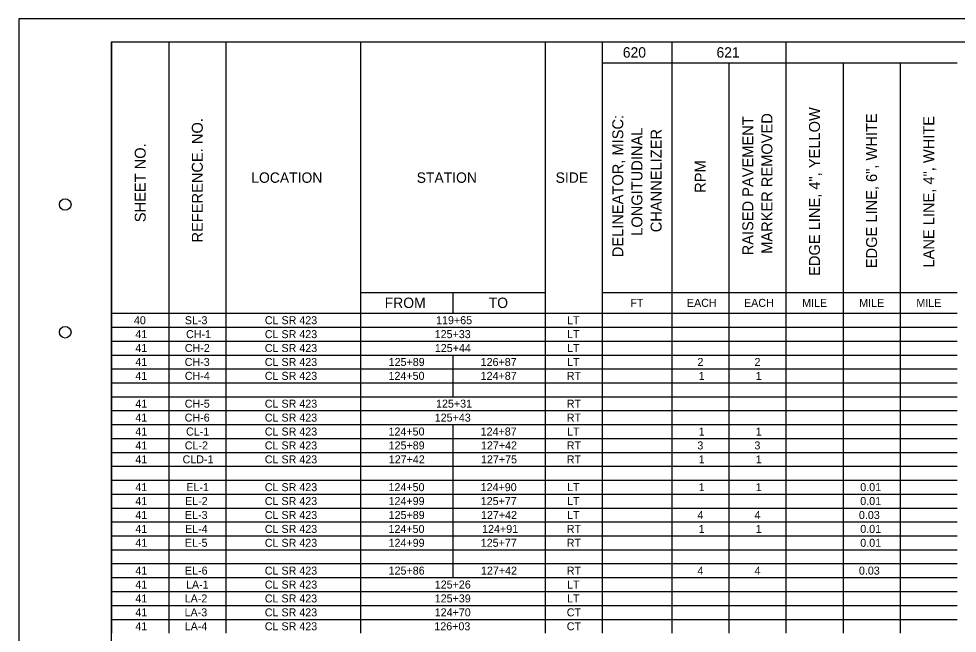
# Model space of a CAD drawing. Extents: x 10.3 to 44.3, y 3.4 to 25.4.
# Drawn here: x 10.31 to 30.51, y 12.17 to 25.4 of the extents above; entities that cross this region are included whole.
import ezdxf

# ---------------------------------------------------------------- set-up
doc = ezdxf.new("R2010")
doc.units = 0
for name, color, linetype in [('SH_Border', 7, 'Continuous'), ('SH_Cut_Line', 7, 'Continuous'), ('SH_Text', 7, 'Continuous')]:
    doc.layers.add(name, color=color, linetype=linetype)

msp = doc.modelspace()

# ---------------------------------------------------------------- linework, layer by layer
at = {"layer": 'SH_Border'}
msp.add_lwpolyline([(12.306, 24.905), (43.806, 24.905), (43.806, 3.905), (12.306, 3.905)], close=True, dxfattribs=at)
for centre in [(11.306, 21.405), (11.306, 18.655)]:
    msp.add_circle(centre, 0.125, dxfattribs=at)
at = {"layer": 'SH_Cut_Line'}
msp.add_lwpolyline([(10.306, 3.405), (44.306, 3.405), (44.306, 25.405), (10.306, 25.405)], close=True, dxfattribs=at)
at = {"layer": 'SH_Text'}
for p, q in [((12.306, 24.905), (14.765, 24.905)), ((12.306, 24.905), (12.306, 12.173)), ((13.536, 24.905), (13.536, 12.173)), ((14.765, 24.905), (21.637, 24.905)), ((14.765, 24.905), (14.765, 12.173)), ((17.665, 24.905), (17.665, 12.173)), ((21.637, 24.905), (26.823, 24.905)), ((21.637, 24.905), (21.637, 12.173)), ((22.867, 24.905), (22.867, 12.173)), ((24.364, 24.905), (24.364, 12.173)), ((26.823, 24.905), (28.053, 24.905)), ((26.823, 24.905), (26.823, 12.173)), ((28.053, 24.905), (30.512, 24.905)), ((22.867, 24.455), (26.823, 24.455)), ((25.594, 24.455), (25.594, 12.173)), ((26.823, 24.455), (28.053, 24.455)), ((28.053, 24.455), (30.512, 24.455)), ((28.053, 24.455), (28.053, 12.173)), ((29.282, 24.455), (29.282, 12.173)), ((17.665, 19.512), (21.637, 19.512)), ((19.651, 19.512), (19.651, 19.063)), ((22.867, 19.512), (26.823, 19.512)), ((26.823, 19.512), (28.053, 19.512)), ((28.053, 19.512), (30.512, 19.512)), ((12.306, 19.063), (14.765, 19.063)), ((14.765, 19.063), (21.637, 19.063)), ((21.637, 19.063), (26.823, 19.063)), ((26.823, 19.063), (28.053, 19.063)), ((28.053, 19.063), (30.512, 19.063)), ((12.306, 18.763), (14.765, 18.763)), ((14.765, 18.763), (21.637, 18.763)), ((21.637, 18.763), (26.823, 18.763)), ((26.823, 18.763), (28.053, 18.763)), ((28.053, 18.763), (30.512, 18.763)), ((12.306, 18.464), (14.765, 18.464)), ((14.765, 18.464), (21.637, 18.464)), ((21.637, 18.464), (26.823, 18.464)), ((26.823, 18.464), (28.053, 18.464)), ((28.053, 18.464), (30.512, 18.464)), ((12.306, 18.164), (14.765, 18.164)), ((14.765, 18.164), (21.637, 18.164)), ((19.651, 18.164), (19.651, 17.265)), ((21.637, 18.164), (26.823, 18.164)), ((26.823, 18.164), (28.053, 18.164)), ((28.053, 18.164), (30.512, 18.164)), ((12.306, 17.865), (14.765, 17.865)), ((14.765, 17.865), (21.637, 17.865)), ((21.637, 17.865), (26.823, 17.865)), ((26.823, 17.865), (28.053, 17.865)), ((28.053, 17.865), (30.512, 17.865)), ((12.306, 17.565), (14.765, 17.565)), ((14.765, 17.565), (21.637, 17.565)), ((21.637, 17.565), (26.823, 17.565)), ((26.823, 17.565), (28.053, 17.565)), ((28.053, 17.565), (30.512, 17.565)), ((12.306, 17.265), (14.765, 17.265)), ((14.765, 17.265), (21.637, 17.265)), ((21.637, 17.265), (26.823, 17.265)), ((26.823, 17.265), (28.053, 17.265)), ((28.053, 17.265), (30.512, 17.265)), ((12.306, 16.966), (14.765, 16.966)), ((14.765, 16.966), (21.637, 16.966)), ((21.637, 16.966), (26.823, 16.966)), ((26.823, 16.966), (28.053, 16.966)), ((28.053, 16.966), (30.512, 16.966)), ((12.306, 16.666), (14.765, 16.666)), ((14.765, 16.666), (21.637, 16.666)), ((19.651, 16.666), (19.651, 13.371)), ((21.637, 16.666), (26.823, 16.666)), ((26.823, 16.666), (28.053, 16.666)), ((28.053, 16.666), (30.512, 16.666)), ((12.306, 16.367), (14.765, 16.367)), ((14.765, 16.367), (21.637, 16.367)), ((21.637, 16.367), (26.823, 16.367)), ((26.823, 16.367), (28.053, 16.367)), ((28.053, 16.367), (30.512, 16.367)), ((12.306, 16.067), (14.765, 16.067)), ((14.765, 16.067), (21.637, 16.067)), ((21.637, 16.067), (26.823, 16.067)), ((26.823, 16.067), (28.053, 16.067)), ((28.053, 16.067), (30.512, 16.067)), ((12.306, 15.768), (14.765, 15.768)), ((14.765, 15.768), (21.637, 15.768)), ((21.637, 15.768), (26.823, 15.768)), ((26.823, 15.768), (28.053, 15.768)), ((28.053, 15.768), (30.512, 15.768)), ((12.306, 15.468), (14.765, 15.468)), ((14.765, 15.468), (21.637, 15.468)), ((21.637, 15.468), (26.823, 15.468)), ((26.823, 15.468), (28.053, 15.468)), ((28.053, 15.468), (30.512, 15.468)), ((12.306, 15.168), (14.765, 15.168)), ((14.765, 15.168), (21.637, 15.168)), ((21.637, 15.168), (26.823, 15.168)), ((26.823, 15.168), (28.053, 15.168)), ((28.053, 15.168), (30.512, 15.168)), ((12.306, 14.869), (14.765, 14.869)), ((14.765, 14.869), (21.637, 14.869)), ((21.637, 14.869), (26.823, 14.869)), ((26.823, 14.869), (28.053, 14.869)), ((28.053, 14.869), (30.512, 14.869)), ((12.306, 14.569), (14.765, 14.569)), ((14.765, 14.569), (21.637, 14.569)), ((21.637, 14.569), (26.823, 14.569)), ((26.823, 14.569), (28.053, 14.569)), ((28.053, 14.569), (30.512, 14.569)), ((12.306, 14.27), (14.765, 14.27)), ((14.765, 14.27), (21.637, 14.27)), ((21.637, 14.27), (26.823, 14.27)), ((26.823, 14.27), (28.053, 14.27)), ((28.053, 14.27), (30.512, 14.27)), ((12.306, 13.97), (14.765, 13.97)), ((14.765, 13.97), (21.637, 13.97)), ((21.637, 13.97), (26.823, 13.97)), ((26.823, 13.97), (28.053, 13.97)), ((28.053, 13.97), (30.512, 13.97)), ((12.306, 13.671), (14.765, 13.671)), ((14.765, 13.671), (21.637, 13.671)), ((21.637, 13.671), (26.823, 13.671)), ((26.823, 13.671), (28.053, 13.671)), ((28.053, 13.671), (30.512, 13.671)), ((12.306, 13.371), (14.765, 13.371)), ((14.765, 13.371), (21.637, 13.371)), ((21.637, 13.371), (26.823, 13.371)), ((26.823, 13.371), (28.053, 13.371)), ((28.053, 13.371), (30.512, 13.371)), ((12.306, 13.071), (14.765, 13.071)), ((14.765, 13.071), (21.637, 13.071)), ((21.637, 13.071), (26.823, 13.071)), ((26.823, 13.071), (28.053, 13.071)), ((28.053, 13.071), (30.512, 13.071)), ((12.306, 12.772), (14.765, 12.772)), ((14.765, 12.772), (21.637, 12.772)), ((21.637, 12.772), (26.823, 12.772)), ((26.823, 12.772), (28.053, 12.772)), ((28.053, 12.772), (30.512, 12.772)), ((12.306, 12.472), (14.765, 12.472)), ((14.765, 12.472), (21.637, 12.472)), ((21.637, 12.472), (26.823, 12.472)), ((26.823, 12.472), (28.053, 12.472)), ((28.053, 12.472), (30.512, 12.472))]:
    msp.add_line(p, q, dxfattribs=at)

# ---------------------------------------------------------------- texts
for s, height, p in [('620', 0.2239, (23.311, 24.568)), ('621', 0.2239, (25.328, 24.568)), ('LOCATION', 0.2239, (15.312, 21.872)), ('STATION', 0.2239, (18.873, 21.872)), ('SIDE', 0.2239, (21.865, 21.872)), ('FROM', 0.2239, (18.185, 19.176)), ('TO', 0.2239, (20.424, 19.176)), ('FT', 0.1723, (23.473, 19.201)), ('EACH', 0.1723, (24.692, 19.201)), ('EACH', 0.1723, (25.921, 19.201)), ('MILE', 0.1723, (27.173, 19.201)), ('MILE', 0.1723, (28.402, 19.201)), ('MILE', 0.1723, (29.632, 19.201)), ('40', 0.1723, (12.785, 18.827)), ('SL-3', 0.1723, (13.882, 18.827)), ('CL SR 423', 0.1723, (15.604, 18.827)), ('119+65', 0.1723, (19.291, 18.827)), ('LT', 0.1723, (22.11, 18.827)), ('41', 0.1723, (12.816, 18.527)), ('CH-1', 0.1723, (13.908, 18.527)), ('CL SR 423', 0.1723, (15.604, 18.527)), ('125+33', 0.1723, (19.261, 18.527)), ('LT', 0.1723, (22.11, 18.527)), ('41', 0.1723, (12.816, 18.228)), ('CH-2', 0.1723, (13.881, 18.228)), ('CL SR 423', 0.1723, (15.604, 18.228)), ('125+44', 0.1723, (19.264, 18.228)), ('LT', 0.1723, (22.11, 18.228)), ('41', 0.1723, (12.816, 17.928)), ('CH-3', 0.1723, (13.879, 17.928)), ('CL SR 423', 0.1723, (15.604, 17.928)), ('125+89', 0.1723, (18.27, 17.928)), ('126+87', 0.1723, (20.251, 17.928)), ('LT', 0.1723, (22.11, 17.928)), ('2', 0.172, (24.918, 17.928)), ('2', 0.172, (26.147, 17.928)), ('41', 0.1723, (12.816, 17.629)), ('CH-4', 0.1723, (13.882, 17.629)), ('CL SR 423', 0.1723, (15.604, 17.629)), ('124+50', 0.1723, (18.267, 17.629)), ('124+87', 0.1723, (20.251, 17.629)), ('RT', 0.1723, (22.105, 17.629)), ('1', 0.172, (24.945, 17.629)), ('1', 0.172, (26.174, 17.629)), ('41', 0.1723, (12.816, 17.03)), ('CH-5', 0.1723, (13.88, 17.03)), ('CL SR 423', 0.1723, (15.604, 17.03)), ('125+31', 0.1723, (19.29, 17.03)), ('RT', 0.1723, (22.105, 17.03)), ('41', 0.1723, (12.816, 16.73)), ('CH-6', 0.1723, (13.879, 16.73)), ('CL SR 423', 0.1723, (15.604, 16.73)), ('125+43', 0.1723, (19.262, 16.73)), ('RT', 0.1723, (22.105, 16.73)), ('41', 0.1723, (12.816, 16.43)), ('CL-1', 0.1723, (13.908, 16.43)), ('CL SR 423', 0.1723, (15.604, 16.43)), ('124+50', 0.1723, (18.267, 16.43)), ('124+87', 0.1723, (20.251, 16.43)), ('LT', 0.1723, (22.11, 16.43)), ('1', 0.172, (24.945, 16.43)), ('1', 0.172, (26.174, 16.43)), ('41', 0.1723, (12.816, 16.131)), ('CL-2', 0.1723, (13.881, 16.131)), ('CL SR 423', 0.1723, (15.604, 16.131)), ('125+89', 0.1723, (18.27, 16.131)), ('127+42', 0.1723, (20.258, 16.131)), ('RT', 0.1723, (22.105, 16.131)), ('3', 0.172, (24.916, 16.131)), ('3', 0.172, (26.145, 16.131)), ('41', 0.1723, (12.816, 15.831)), ('CLD-1', 0.1723, (13.833, 15.831)), ('CL SR 423', 0.1723, (15.604, 15.831)), ('127+42', 0.1723, (18.272, 15.831)), ('127+75', 0.1723, (20.258, 15.831)), ('RT', 0.1723, (22.105, 15.831)), ('1', 0.172, (24.945, 15.831)), ('1', 0.172, (26.174, 15.831)), ('41', 0.1723, (12.816, 15.232)), ('EL-1', 0.1723, (13.913, 15.232)), ('CL SR 423', 0.1723, (15.604, 15.232)), ('124+50', 0.1723, (18.267, 15.232)), ('124+90', 0.1723, (20.251, 15.232)), ('LT', 0.1723, (22.11, 15.232)), ('1', 0.172, (24.945, 15.232)), ('1', 0.172, (26.174, 15.232)), ('0.01', 0.1723, (28.424, 15.232)), ('41', 0.1723, (12.816, 14.933)), ('EL-2', 0.1723, (13.886, 14.933)), ('CL SR 423', 0.1723, (15.604, 14.933)), ('124+99', 0.1723, (18.268, 14.933)), ('125+77', 0.1723, (20.253, 14.933)), ('LT', 0.1723, (22.11, 14.933)), ('0.01', 0.1723, (28.424, 14.933)), ('41', 0.1723, (12.816, 14.633)), ('EL-3', 0.1723, (13.884, 14.633)), ('CL SR 423', 0.1723, (15.604, 14.633)), ('125+89', 0.1723, (18.27, 14.633)), ('127+42', 0.1723, (20.258, 14.633)), ('LT', 0.1723, (22.11, 14.633)), ('4', 0.172, (24.919, 14.633)), ('4', 0.172, (26.148, 14.633)), ('0.03', 0.1723, (28.395, 14.633)), ('41', 0.1723, (12.816, 14.333)), ('EL-4', 0.1723, (13.886, 14.333)), ('CL SR 423', 0.1723, (15.604, 14.333)), ('124+50', 0.1723, (18.267, 14.333)), ('124+91', 0.1723, (20.282, 14.333)), ('RT', 0.1723, (22.105, 14.333)), ('1', 0.172, (24.945, 14.333)), ('1', 0.172, (26.174, 14.333)), ('0.01', 0.1723, (28.424, 14.333)), ('41', 0.1723, (12.816, 14.034)), ('EL-5', 0.1723, (13.884, 14.034)), ('CL SR 423', 0.1723, (15.604, 14.034)), ('124+99', 0.1723, (18.268, 14.034)), ('125+77', 0.1723, (20.253, 14.034)), ('RT', 0.1723, (22.105, 14.034)), ('0.01', 0.1723, (28.424, 14.034)), ('41', 0.1723, (12.816, 13.435)), ('EL-6', 0.1723, (13.884, 13.435)), ('CL SR 423', 0.1723, (15.604, 13.435)), ('125+86', 0.1723, (18.269, 13.435)), ('127+42', 0.1723, (20.258, 13.435)), ('RT', 0.1723, (22.105, 13.435)), ('4', 0.172, (24.919, 13.435)), ('4', 0.172, (26.148, 13.435)), ('0.03', 0.1723, (28.395, 13.435)), ('41', 0.1723, (12.816, 13.135)), ('LA-1', 0.1723, (13.906, 13.135)), ('CL SR 423', 0.1723, (15.604, 13.135)), ('125+26', 0.1723, (19.263, 13.135)), ('LT', 0.1723, (22.11, 13.135)), ('41', 0.1723, (12.816, 12.836)), ('LA-2', 0.1723, (13.879, 12.836)), ('CL SR 423', 0.1723, (15.604, 12.836)), ('125+39', 0.1723, (19.262, 12.836)), ('LT', 0.1723, (22.11, 12.836)), ('41', 0.1723, (12.816, 12.536)), ('LA-3', 0.1723, (13.877, 12.536)), ('CL SR 423', 0.1723, (15.604, 12.536)), ('124+70', 0.1723, (19.261, 12.536)), ('CT', 0.1723, (22.105, 12.536)), ('41', 0.1723, (12.816, 12.236)), ('LA-4', 0.1723, (13.88, 12.236)), ('CL SR 423', 0.1723, (15.604, 12.236)), ('126+03', 0.1723, (19.253, 12.236)), ('CT', 0.1723, (22.105, 12.236))]:
    msp.add_text(s, height=height, dxfattribs=at).set_placement(p)
for s, height, p in [('EDGE LINE, 4", YELLOW', 0.23565, (27.556, 19.868)), ('REFERENCE. NO.', 0.23565, (14.268, 20.586)), ('DELINEATOR, MISC:', 0.23565, (23.321, 20.27)), ('RAISED PAVEMENT', 0.23565, (26.12, 20.31)), ('MARKER REMOVED', 0.23565, (26.532, 20.343)), ('EDGE LINE, 6", WHITE', 0.23565, (28.785, 20.034)), ('LANE LINE, 4", WHITE', 0.23565, (30.015, 20.048)), ('LONGITUDINAL', 0.23565, (23.733, 20.732)), ('CHANNELIZER', 0.23565, (24.146, 20.807)), ('SHEET NO.', 0.2356, (13.039, 21.024)), ('RPM', 0.2356, (25.097, 21.657))]:
    msp.add_text(s, height=height, rotation=90, dxfattribs=at).set_placement(p)

doc.saveas('drawing.dxf')
